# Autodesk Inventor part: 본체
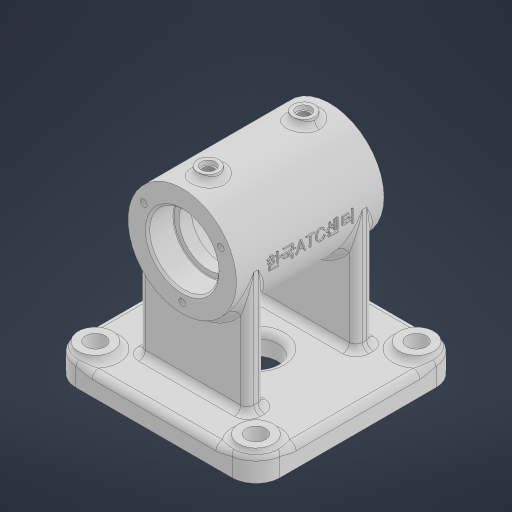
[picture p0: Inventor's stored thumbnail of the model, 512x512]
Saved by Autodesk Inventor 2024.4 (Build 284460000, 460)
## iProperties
Created: 2025-10
Part Number: 본체
Material: 일반
Document SubType Name: Modeling
Designer: user
Density: 1 g/cm^3
Appearance: 기본값
Author: user
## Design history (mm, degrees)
sketch "스케치1"
  geometry: C1 r 25 at (0, 0); 1 further point
  constraints: 1 centre point, 1 coincident
  dimensions: "d0" = 50 diameter of C1
extrude "돌출1" new body sketch "스케치1" stored distance "d1" = 68; taper "d2" = 0 deg
sketch "스케치2"
  geometry: L1 (-25, -34)-(25, -34) reference; L2 (25, 34)-(-25, 34) reference; L3 (0, 34)-(0, -34); L4 (16, 34)-(16, 22.3); L5 (15.7, 22)-(13.5, 22); L6 (13.5, 22)-(13.5, 16.258); L7 (13.5, 16.258)-(20, 5); L8 (20, 5)-(20, -5); L9 (20, -5)-(13.5, -16.258); L10 (13.5, -16.258)-(13.5, -22); L11 (13.5, -22)-(15.7, -22); L12 (16, -22.3)-(16, -34); L13 (25, -34)-(25, 34) reference; L14 (16, 34)-(0, 34); L15 (16, -34)-(0, -34); A1 r 0.3 centre (15.7, 22.3) between (15.7, 22) and (16, 22.3); A2 r 0.3 centre (15.7, -22.3) between (16, -22.3) and (15.7, -22); 6 further points
  constraints: 24 end point, 10 point on line, 5 midpoint, 4 perpendicular, 4 point on circle, 4 tangent, 2 centre point, 2 collinear, 1 horizontal alignment, 1 parallel
  dimensions: "d3" = 10 distance of L7.end L8.end; "d4" = 12 distance of L4.start point (16, 22); "d5" = 40 diameter of point (20, 0) point (0, 0); "d6" = 32 diameter of L12 L3; "d7" = 27 diameter of L10 L3; "d8" = 0.3 radius of A1; "d9" = 30 deg angle of L3 L7; "d10" = 0.3 radius of A2
revolve "회전1" sketch "스케치2" stored, may be unused: angle "d11" = 90 deg
chamfer "모따기1" distance "d12" = 1; stored, may be unused: second distance "d13" = 2, angle "d14" = 45 deg
fillet "모깎기1" dims "d15" = 3
sketch "스케치3"
  geometry: L1 (-25, -34)-(25, -34) reference; L2 (25, 34)-(-25, 34) reference; L3 (-17, 34)-(-16, 33) reference; L4 (-16, 33)-(-16, 22.3) reference; L5 (-15.7, 22)-(-13.5, 22) reference; L6 (-13.5, 22)-(-13.5, 16.258) reference; L7 (-13.5, 16.258)-(-19.598, 5.696) reference; L8 (-20, 4.196)-(-20, -4.196) reference; L9 (-19.598, -5.696)-(-13.5, -16.258) reference; L10 (-13.5, -16.258)-(-13.5, -22) reference; L11 (-13.5, -22)-(-15.7, -22) reference; L12 (-16, -22.3)-(-16, -33) reference; L13 (-16, -33)-(-17, -34) reference; L14 (-17, -34)-(-25, -34) reference; L15 (-25, -34)-(-25, 34) reference; L16 (-25, 34)-(-17, 34) reference; L17 (16, 33)-(17, 34) reference; L18 (17, 34)-(25, 34) reference; L19 (25, 34)-(25, -34) reference; L20 (25, -34)-(17, -34) reference; L21 (17, -34)-(16, -33) reference; L22 (16, -33)-(16, -22.3) reference; L23 (15.7, -22)-(13.5, -22) reference; L24 (13.5, -22)-(13.5, -16.258) reference; L25 (13.5, -16.258)-(19.598, -5.696) reference; L26 (20, -4.196)-(20, 4.196) reference; L27 (19.598, 5.696)-(13.5, 16.258) reference; L28 (13.5, 16.258)-(13.5, 22) reference; L29 (13.5, 22)-(15.7, 22) reference; L30 (16, 22.3)-(16, 33) reference; L31 (25, 22)-(28, 22); L32 (28, 22)-(28, 27); L33 (28, 27)-(25, 27); L34 (25, 27)-(23, 27); L35 (23, 27)-(23, 22); L36 (23, 22)-(25, 22); A1 r 0.3 centre (-15.7, 22.3) between (-16, 22.3) and (-15.7, 22) reference; A2 r 3 centre (-17, 4.196) between (-19.598, 5.696) and (-20, 4.196) reference; A3 r 3 centre (-17, -4.196) between (-20, -4.196) and (-19.598, -5.696) reference; A4 r 0.3 centre (-15.7, -22.3) between (-15.7, -22) and (-16, -22.3) reference; A5 r 0.3 centre (15.7, -22.3) between (16, -22.3) and (15.7, -22) reference; A6 r 3 centre (17, -4.196) between (19.598, -5.696) and (20, -4.196) reference; A7 r 3 centre (17, 4.196) between (20, 4.196) and (19.598, 5.696) reference; A8 r 0.3 centre (15.7, 22.3) between (15.7, 22) and (16, 22.3) reference; 1 further point
  constraints: 12 end point, 3 horizontal, 2 perpendicular, 1 parallel, 1 point on line
  dimensions: "d16" = 12 vertical distance of L2.start L31.end; "d17" = 3 distance from line of L19 L32.end; "d18" = 10 diameter of L32.end L31; "d19" = 5 distance between parallel lines of L35 L32
revolve "회전2" sketch "스케치3" stored, may be unused: angle "d20" = 90 deg
fillet "모깎기2" dims "d21" = 3
sketch "스케치4"
  geometry: A1 r 5 centre (0, 0) between (0, -5) and (0, 5) reference; A2 r 5 centre (0, 0) between (0, 5) and (0, -5) reference; A3 r 5 centre (0, 44) between (0, 49) and (0, 39) reference; A4 r 5 centre (0, 44) between (0, 39) and (0, 49) reference; 3 further points
  constraints: 2 coincident
hole "구멍1" sketch "스케치4" at (0, 44), (0, 0) diameter "d22" = 5.1881; stored, may be unused: countersink angle "d26" = 90 deg, drill point angle "d28" = 0 deg; dims "d23" = 12, "d24" = 6.6, "d25" = 2, "d27" = 11.8
node "작업 평면1"
sketch "스케치5"
  geometry: L1 (47, -25)-(-47, -25); L2 (-47, -25)-(-47, 69); L3 (-47, 69)-(47, 69); L4 (47, 69)-(47, -25); L5 (47, -25)-(-47, 69); L6 (-47, -25)-(47, 69); L7 (37, -15)-(-37, -15); L8 (-37, -15)-(-37, 59); L9 (-37, 59)-(37, 59); L10 (37, 59)-(37, -15); L11 (37, -15)-(-37, 59); L12 (-37, -15)-(37, 59); C1 r 8 at (-37, -15); C2 r 4.5 at (-37, -15); C3 r 4.5 at (37, -15); C4 r 4.472 at (37, -15); C5 r 4.5 at (37, 59); C6 r 8 at (37, 59); C7 r 8 at (-37, 59); C8 r 4.5 at (-37, 59); C9 r 8 at (37, -15); 1 further point
  constraints: 24 end point, 9 centre point, 9 coincident, 6 equal radius, 4 midpoint, 4 parallel, 4 perpendicular, 2 horizontal
  dimensions: "d30" = 94 distance of L1.end L2.end; "d31" = 16 diameter of C1; "d32" = 9 diameter of C2; "d33" = 74 distance of L7.start L7.end
extrude "돌출2" join sketch "스케치5" distance "d34" = 13; taper "d35" = 0 deg
extrude "돌출3" join sketch "스케치5" distance "d36" = 10; taper "d37" = 0 deg
fillet "모깎기3" dims "d38" = 11
fillet "모깎기4" dims "d39" = 3
fillet "모깎기5" dims "d40" = 3
sketch "스케치6"
  geometry: L1 (-19.389, 25)-(-56, 25); L2 (-0.488, 21)-(-56, 21); L3 (-0.488, 29)-(-56, 29); L4 (-56, 29)-(-56, 21); L5 (28, 27)-(28, 25.3) reference; L6 (28, 25.3)-(26, 25.3) reference; L7 (26, 25.3)-(26, 24.594) reference; L8 (26, 24.594)-(16, 24.594) reference; L9 (16, 24.594)-(16, 33) reference; L10 (16, 33)-(17, 34) reference; L11 (17, 34)-(25, 34) reference; L12 (25, 34)-(25, 30) reference; L13 (19.598, 5.696)-(13.5, 16.258) reference; L14 (13.5, 16.258)-(13.5, 19.406) reference; L15 (13.5, 19.406)-(26, 19.406) reference; L16 (26, 19.406)-(26, 18.7) reference; L17 (26, 18.7)-(28, 18.7) reference; L18 (28, 18.7)-(28, 17) reference; L19 (25, 14)-(25, -14) reference; L20 (28, -17)-(28, -18.7) reference; L21 (28, -18.7)-(26, -18.7) reference; L22 (26, -18.7)-(26, -19.406) reference; L23 (26, -19.406)-(13.5, -19.406) reference; L24 (13.5, -19.406)-(13.5, -16.258) reference; L25 (13.5, -16.258)-(19.598, -5.696) reference; L26 (20, -4.196)-(20, 4.196) reference; L27 (-16, -33)-(-17, -34) reference; L28 (-17, -34)-(-25, -34) reference; L29 (-25, -34)-(-25, 34) reference; L30 (-25, 34)-(-17, 34) reference; L31 (-17, 34)-(-16, 33) reference; L32 (-16, 33)-(-16, 22.3) reference; L33 (-15.7, 22)-(-13.5, 22) reference; L34 (-13.5, 22)-(-13.5, 16.258) reference; L35 (-13.5, 16.258)-(-19.598, 5.696) reference; L36 (-20, 4.196)-(-20, -4.196) reference; L37 (-19.598, -5.696)-(-13.5, -16.258) reference; L38 (-13.5, -16.258)-(-13.5, -22) reference; L39 (-13.5, -22)-(-15.7, -22) reference; L40 (-16, -22.3)-(-16, -33) reference; L41 (17, -34)-(16, -33) reference; L42 (16, -33)-(16, -24.594) reference; L43 (16, -24.594)-(26, -24.594) reference; L44 (26, -24.594)-(26, -25.3) reference; L45 (26, -25.3)-(28, -25.3) reference; L46 (28, -25.3)-(28, -27) reference; L47 (25, -30)-(25, -34) reference; L48 (25, -34)-(17, -34) reference; L49 (-56, 44)-(-56, -44) reference; L50 (-59, -47)-(-66, -47) reference; L51 (-66, -47)-(-66, 47) reference; L52 (-66, 47)-(-59, 47) reference; A1 r 3 centre (17, 4.196) between (20, 4.196) and (19.598, 5.696) reference; A2 r 3 centre (17, -4.196) between (19.598, -5.696) and (20, -4.196) reference; A3 r 0.3 centre (-15.7, 22.3) between (-16, 22.3) and (-15.7, 22) reference; A4 r 3 centre (-17, 4.196) between (-19.598, 5.696) and (-20, 4.196) reference; A5 r 3 centre (-17, -4.196) between (-20, -4.196) and (-19.598, -5.696) reference; A6 r 0.3 centre (-15.7, -22.3) between (-15.7, -22) and (-16, -22.3) reference; A7 r 3 centre (-59, 44) between (-56, 44) and (-59, 47) reference; A8 r 3 centre (-59, -44) between (-59, -47) and (-56, -44) reference; 3 further points; 1 other entity
  constraints: 8 end point, 2 parallel, 2 point on line, 1 horizontal, 1 vertical, 7 other
  dimensions: "d42" = 4 distance between parallel lines of L1 L2; "d43" = 4 distance between parallel lines of L1 L3; "d44" = 21 distance from line of L2 point (0, 0)
  node "절단 모서리 투영3"
node "작업 평면2"
sketch "스케치8"
  geometry: 2 further points
  constraints: 1 coincident
hole "구멍2" sketch "스케치8" at (0, 22) diameter "d52" = 20; stored, may be unused: countersink angle "d56" = 90 deg, drill point angle "d58" = 0 deg; dims "d53" = 12, "d54" = 6.6, "d55" = 2, "d57" = 8
fillet "모깎기6" dims "d59" = 3
node "작업 평면3"
sketch "스케치9"
  geometry: C1 r 13 at (0, -22) reference; C2 r 6 at (0, -22); 1 further point
  constraints: 1 centre point, 1 coincident
  dimensions: "d61" = 12 diameter of C2
extrude "돌출5" join sketch "스케치9" stored distance "d62" = 13; taper "d63" = 0 deg
fillet "모깎기7" dims "d64" = 3
sketch "스케치10"
  geometry: A1 r 6 centre (0, 22) between (0, 28) and (0, 16) reference; 1 further point
  constraints: 1 coincident
hole "구멍3" sketch "스케치10" at (0, 22) diameter "d65" = 5.1881; stored, may be unused: countersink angle "d69" = 90 deg, drill point angle "d71" = 0 deg; dims "d66" = 12, "d67" = 4, "d68" = 2, "d70" = 28.5
sketch "스케치11"
  geometry: L1 (-63.097, 29)-(6.356, 29); 1 further point
  constraints: 2 end point, 1 horizontal
  dimensions: "d72" = 29 distance from line of L1 point (0, 0)
feature "리브1" sketch "스케치11" dims "d73" = 8, "d74" = 25, "d75" = 0, "d76" = 0, "d77" = 1, "d78" = 1
fillet "모깎기8" dims "d79" = 3
fillet "모깎기14" dims "d85" = 3
fillet "모깎기15" dims "d86" = 3
sketch "스케치7" dims "d0" = 50
  geometry: L1 (-66, 36)-(-66, -36) reference; 3 further points
  constraints: 1 coincident, 1 horizontal alignment, 1 midpoint, 1 other
  dimensions: "d87" = 66 distance from line of L1 point (0, 0)
feature "엠보싱1" sketch "스케치7" dims "d0" = 50, "d3" = 10, "d4" = 12, "d5" = 40, "d6" = 32, "d7" = 27, "d8" = 0.3, "d9" = 30 deg, "d10" = 0.3, "d50" = 0.5, "d51" = 0
sketch "스케치12" dims "d88" = 41
  geometry: C1 r 25 at (0, 0) reference; C2 r 17 at (0, 0) reference; 4 further points
  constraints: 2 vertical alignment, 1 coincident, 6 other
  dimensions: "d91" = 360 deg dimension on point (0, 0) point (0, -20.5) (derived)
hole "구멍4" sketch "스케치12" at (0, -20.5), (17.754, 10.25), (-17.754, 10.25) diameter "d93" = 3.242; stored, may be unused: countersink angle "d97" = 82 deg, drill point angle "d99" = 118 deg; dims "d94" = 8, "d95" = 3.023, "d96" = 2, "d98" = 10
node "솔리드1"
mirror "미러1"
mirror "미러2"
mirror "미러3"
mirror "미러4"
node "투영된 루프1"
node "투영된 루프2"
node "절단 모서리 투영1"
node "절단 모서리 투영2"
feature "A9D066F2-1C7D-4E18-AEED-F7BC21143FA4" dims "d52" = 20, "d53" = 12, "d54" = 6.6, "d55" = 2, "d56" = 90 deg, "d57" = 8, "d58" = 0
other parameters: "d29" = -94, "d60" = -56
